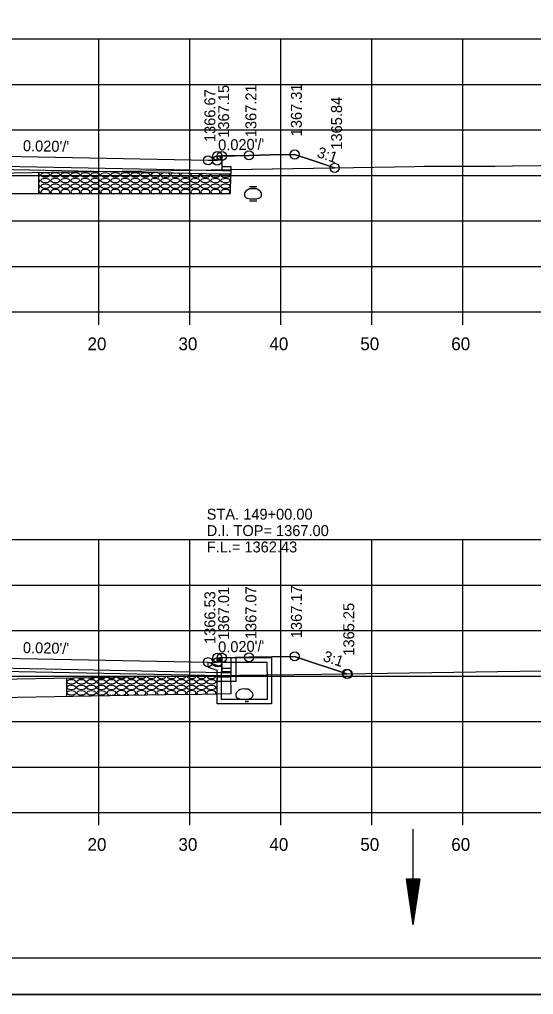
# Model space of a CAD drawing. Extents: x 1374311 to 1383814, y 384102 to 406278.
# Drawn here: x 1381639.9 to 1381696.4, y 391364.8 to 391471.9 of the extents above; entities that cross this region are included whole.
import ezdxf

# ---------------------------------------------------------------- set-up
doc = ezdxf.new("R2010")
doc.units = 0
for name, color, linetype in [('R_Axis', 7, 'Continuous'), ('R_Axis Annot', 7, 'Continuous'), ('R_Border', 7, 'Continuous'), ('R_Draft', 7, 'Continuous'), ('R_Exist Surface', 7, 'Continuous'), ('R_Fin Surface', 7, 'Continuous'), ('R_Grid', 7, 'Continuous'), ('R_No Plot', 7, 'Continuous'), ('R_Water', 7, 'Continuous'), ('R_Water Annot', 7, 'Continuous'), ('R_Xsect Elev', 7, 'Continuous'), ('R_Xsect Slope', 7, 'Continuous')]:
    doc.layers.add(name, color=color, linetype=linetype)

msp = doc.modelspace()

# ---------------------------------------------------------------- linework, layer by layer
at = {"layer": 'R_Axis'}
for p, q in [((1381488.66, 391439.74), (1381768.66, 391439.74)), ((1381648.66, 391438.34), (1381648.66, 391439.74)), ((1381658.66, 391438.34), (1381658.66, 391439.74)), ((1381668.66, 391438.34), (1381668.66, 391439.74)), ((1381678.66, 391438.34), (1381678.66, 391439.74)), ((1381688.66, 391438.34), (1381688.66, 391439.74)), ((1381488.66, 391384.74), (1381768.66, 391384.74)), ((1381648.66, 391383.34), (1381648.66, 391384.74)), ((1381658.66, 391383.34), (1381658.66, 391384.74)), ((1381668.66, 391383.34), (1381668.66, 391384.74)), ((1381678.66, 391383.34), (1381678.66, 391384.74)), ((1381688.66, 391383.34), (1381688.66, 391384.74))]:
    msp.add_line(p, q, dxfattribs=at)
at = {"layer": 'R_Border'}
msp.add_line((1381786.84, 391368.74), (1381470.66, 391368.74), dxfattribs=at)
at = {"layer": 'R_Draft'}
for p, q in [((1381682.43, 391377.42), (1381683.18, 391372.42)), ((1381683.93, 391377.42), (1381682.43, 391377.42)), ((1381682.56, 391377.42), (1381683.18, 391373.25)), ((1381682.68, 391377.42), (1381683.18, 391374.11)), ((1381682.81, 391377.42), (1381683.18, 391374.94)), ((1381682.94, 391377.42), (1381683.18, 391375.79)), ((1381683.06, 391377.42), (1381683.18, 391376.63)), ((1381683.93, 391377.42), (1381683.18, 391372.42)), ((1381683.42, 391377.42), (1381683.18, 391375.79)), ((1381683.68, 391377.42), (1381683.18, 391374.11)), ((1381683.81, 391377.42), (1381683.18, 391373.25)), ((1381683.55, 391377.42), (1381683.18, 391374.94)), ((1381683.3, 391377.42), (1381683.18, 391376.63))]:
    msp.add_line(p, q, dxfattribs=at)
for centre, radius, start, end in [((1381665.09, 391452.66), 0.438, 136.3515, 253.9529), ((1381665.6, 391452.17), 1.15, 43.6485, 136.3515), ((1381666.11, 391452.66), 0.438, 286.0471, 43.6485), ((1381665.6, 391454.44), 2.29, 253.9529, 286.0471), ((1381664.14, 391397.68), 0.438, 136.3515, 253.9529), ((1381664.65, 391397.19), 1.15, 43.6485, 136.3515), ((1381665.17, 391397.68), 0.438, 286.0471, 43.6485), ((1381664.65, 391399.46), 2.29, 253.9529, 286.0471)]:
    msp.add_arc(centre, radius, start, end, dxfattribs=at)
at = {"layer": 'R_Exist Surface'}
for p, q in [((1381665.23, 391453.53), (1381666.02, 391453.52)), ((1381665.23, 391451.95), (1381666.02, 391451.94)), ((1381664.73, 391396.96), (1381665.11, 391396.95))]:
    msp.add_line(p, q, dxfattribs=at)
for points in [[(1381559.74, 391452.62), (1381573.99, 391454.36), (1381575.4, 391454.36), (1381576.5, 391454.37), (1381590.51, 391454.48), (1381603.46, 391454.58), (1381605.2, 391454.59), (1381608.1, 391454.61), (1381615.77, 391454.74), (1381621.68, 391454.81), (1381630.21, 391454.93), (1381637.25, 391454.98), (1381643.34, 391455.11), (1381653.76, 391455.26), (1381656.57, 391455.29), (1381658.85, 391455.32), (1381683.36, 391455.73), (1381684.37, 391455.74), (1381692.19, 391455.77), (1381694.13, 391455.81), (1381706.41, 391455.95)], [(1381570.44, 391398.47), (1381574.42, 391398.46), (1381589.58, 391398.95), (1381591.76, 391398.74), (1381596.26, 391398.17), (1381598.15, 391398.32), (1381598.98, 391399.25), (1381613.79, 391399.74), (1381615.11, 391399.79), (1381620.09, 391399.77), (1381625.2, 391399.68), (1381632.44, 391399.29), (1381633.02, 391399.3), (1381633.51, 391399.32), (1381635.56, 391399.36), (1381655.94, 391399.73), (1381659.94, 391399.76), (1381664.06, 391399.82), (1381673.13, 391399.94), (1381694.93, 391400.26), (1381702.66, 391400.35)]]:
    msp.add_lwpolyline(points, dxfattribs=at)
at = {"layer": 'R_Fin Surface'}
for p, q in [((1381642.02, 391455.08), (1381642.02, 391452.74)), ((1381645.1, 391399.53), (1381645.1, 391397.53))]:
    msp.add_line(p, q, dxfattribs=at)
for points in [[(1381662.17, 391456.52), (1381662.18, 391455.37), (1381663.18, 391455.37), (1381663.17, 391454.87), (1381662.17, 391454.89), (1381628.66, 391455.56), (1381595.15, 391456.16), (1381594.15, 391456.18), (1381594.16, 391456.68), (1381595.16, 391456.65), (1381595.15, 391457.74)], [(1381628.66, 391457.04), (1381643.89, 391456.74), (1381660.66, 391456.4), (1381661.13, 391456.4), (1381661.66, 391456.38), (1381661.67, 391456.62), (1381661.67, 391456.88), (1381661.94, 391456.88), (1381662.17, 391456.88), (1381663.59, 391456.91), (1381665.17, 391456.94), (1381667.53, 391456.99), (1381670.17, 391457.04), (1381672.19, 391456.37), (1381674.59, 391455.57)], [(1381594.08, 391454.51), (1381594.08, 391452.74), (1381663.13, 391452.74), (1381663.17, 391454.87)], [(1381573.67, 391398.46), (1381587.15, 391402.95), (1381592.15, 391402.85), (1381595.15, 391402.79), (1381595.65, 391402.79), (1381595.66, 391402.29), (1381596.66, 391402.31), (1381628.66, 391401.9), (1381660.66, 391401.26), (1381661.66, 391401.24), (1381661.67, 391401.74), (1381662.17, 391401.74), (1381665.17, 391401.8), (1381670.17, 391401.9), (1381675.93, 391399.98)], [(1381662.17, 391401.38), (1381662.18, 391400.23), (1381663.18, 391400.23), (1381663.17, 391399.73), (1381662.17, 391399.75), (1381628.66, 391400.42), (1381595.15, 391400.89), (1381594.15, 391400.91), (1381594.16, 391401.41), (1381595.16, 391401.38), (1381595.15, 391402.48)], [(1381594.06, 391398.44), (1381594.07, 391397.09), (1381613.86, 391397.75), (1381615.14, 391397.79), (1381620.07, 391397.77), (1381625.13, 391397.68), (1381632.41, 391397.29), (1381633.09, 391397.3), (1381633.57, 391397.32), (1381635.6, 391397.36), (1381655.97, 391397.73), (1381659.96, 391397.76), (1381663.21, 391397.81), (1381663.17, 391399.73)]]:
    msp.add_lwpolyline(points, dxfattribs=at)
for centre, start_param, end_param in [((1381641.66, 391454.79), 5.506406, 7.059965), ((1381646.07, 391455.41), 4.548724, 4.931461), ((1381647.17, 391455.41), 4.339441, 5.140744), ((1381648.27, 391455.41), 4.267711, 5.079843), ((1381654.87, 391454.79), 1.829771, 7.517782), ((1381655.97, 391454.79), 2.045494, 7.302059), ((1381657.07, 391454.79), 2.198343, 7.14921), ((1381658.17, 391454.79), 2.325792, 7.021762), ((1381659.27, 391454.79), 2.438875, 6.908679), ((1381660.37, 391454.79), 2.54269, 6.804864), ((1381661.47, 391454.79), 2.64012, 6.707434), ((1381662.57, 391454.79), 2.733011, 6.614542), ((1381641.66, 391454.17), 5.506406, 7.059965), ((1381641.66, 391453.55), 5.506406, 7.059965), ((1381641.66, 391452.93), 5.506406, 7.059965), ((1381642.76, 391452.93), 5.41975, 10.288213), ((1381643.87, 391452.93), 5.41975, 10.288213), ((1381644.97, 391452.93), 5.41975, 10.288213), ((1381646.07, 391452.93), 5.41975, 10.288213), ((1381647.17, 391452.93), 5.41975, 10.288213), ((1381648.27, 391452.93), 5.41975, 10.288213), ((1381649.37, 391452.93), 5.41975, 10.288213), ((1381650.47, 391452.93), 5.41975, 10.288213), ((1381651.57, 391452.93), 5.41975, 10.288213), ((1381652.67, 391452.93), 5.41975, 10.288213), ((1381653.77, 391452.93), 5.41975, 10.288213), ((1381654.87, 391452.93), 5.41975, 10.288213), ((1381655.97, 391452.93), 5.41975, 10.288213), ((1381657.07, 391452.93), 5.41975, 10.288213), ((1381658.17, 391452.93), 5.41975, 10.288213), ((1381659.27, 391452.93), 5.41975, 10.288213), ((1381660.37, 391452.93), 5.41975, 10.288213), ((1381661.47, 391452.93), 5.41975, 10.288213), ((1381662.57, 391452.93), 5.41975, 10.288213), ((1381645.63, 391399.73), 4.001346, 5.493252), ((1381646.73, 391399.73), 3.894207, 5.600391), ((1381647.83, 391399.73), 3.796303, 5.698295), ((1381648.93, 391399.73), 3.704829, 5.78977), ((1381650.03, 391399.73), 3.618011, 5.876587), ((1381651.13, 391399.73), 3.534628, 5.95997), ((1381652.23, 391399.73), 3.453777, 6.040822), ((1381653.33, 391399.73), 3.374749, 6.119849), ((1381654.43, 391399.73), 3.29696, 6.197639), ((1381655.53, 391399.73), 3.219898, 6.271446), ((1381656.63, 391399.73), 3.150088, 6.307116), ((1381657.73, 391399.73), 3.114409, 6.300849), ((1381657.73, 391399.73), 0.017664, 0.059611), ((1381658.83, 391399.73), 3.078673, 6.363554), ((1381658.83, 391399.73), 0.080369, 0.095346), ((1381659.93, 391399.73), 3.042836, 6.414368), ((1381659.93, 391399.73), 0.131183, 0.143279), ((1381661.03, 391399.73), 2.991936, 6.398491), ((1381662.13, 391399.11), 2.832405, 3.45078), ((1381662.13, 391399.73), 3.034539, 3.45078), ((1381650.03, 391397.88), 4.881698, 10.318639), ((1381650.03, 391397.88), 4.035454, 4.6129), ((1381651.13, 391397.88), 5.164572, 10.264554), ((1381651.13, 391397.88), 3.981369, 4.330026), ((1381652.23, 391397.88), 5.325563, 10.21346), ((1381652.23, 391397.88), 3.930275, 4.169036), ((1381653.33, 391397.88), 5.453815, 10.164794), ((1381653.33, 391397.88), 3.881609, 4.040784), ((1381654.43, 391397.88), 5.565077, 10.118139), ((1381654.43, 391397.88), 3.834954, 3.929521), ((1381655.53, 391397.88), 5.66574, 10.073173), ((1381655.53, 391397.88), 3.789988, 3.828858), ((1381656.63, 391397.88), 1.325946, 3.746458), ((1381656.63, 391397.88), 5.710747, 7.609131), ((1381657.73, 391397.88), 5.753046, 9.930366), ((1381657.73, 391397.88), 3.647181, 3.704158), ((1381658.83, 391397.88), 5.794284, 9.845926), ((1381658.83, 391397.88), 3.562741, 3.66292), ((1381659.93, 391397.88), 5.846214, 9.764299), ((1381659.93, 391397.88), 3.481114, 3.622603), ((1381661.03, 391397.88), 5.915217, 9.68472), ((1381661.03, 391397.88), 3.401535, 3.566553), ((1381662.13, 391398.49), 2.832405, 3.45078), ((1381662.13, 391397.88), 2.832405, 3.45078)]:
    msp.add_ellipse(centre, major_axis=(0.5, 0), ratio=0.517889, start_param=start_param, end_param=end_param, dxfattribs=at)
for centre in [(1381642.76, 391454.79), (1381643.87, 391454.79), (1381644.97, 391454.79), (1381646.07, 391454.79), (1381647.17, 391454.79), (1381648.27, 391454.79), (1381649.37, 391454.79), (1381650.47, 391454.79), (1381651.57, 391454.79), (1381652.67, 391454.79), (1381653.77, 391454.79), (1381642.76, 391454.17), (1381642.76, 391453.55), (1381643.87, 391454.17), (1381643.87, 391453.55), (1381644.97, 391454.17), (1381644.97, 391453.55), (1381646.07, 391454.17), (1381646.07, 391453.55), (1381647.17, 391454.17), (1381647.17, 391453.55), (1381648.27, 391454.17), (1381648.27, 391453.55), (1381649.37, 391454.17), (1381649.37, 391453.55), (1381650.47, 391454.17), (1381650.47, 391453.55), (1381651.57, 391454.17), (1381651.57, 391453.55), (1381652.67, 391454.17), (1381652.67, 391453.55), (1381653.77, 391454.17), (1381653.77, 391453.55), (1381654.87, 391454.17), (1381654.87, 391453.55), (1381655.97, 391454.17), (1381655.97, 391453.55), (1381657.07, 391454.17), (1381657.07, 391453.55), (1381658.17, 391454.17), (1381658.17, 391453.55), (1381659.27, 391454.17), (1381659.27, 391453.55), (1381660.37, 391454.17), (1381660.37, 391453.55), (1381661.47, 391454.17), (1381661.47, 391453.55), (1381662.57, 391454.17), (1381662.57, 391453.55), (1381645.63, 391399.11), (1381645.63, 391398.49), (1381646.73, 391399.11), (1381646.73, 391398.49), (1381647.83, 391399.11), (1381647.83, 391398.49), (1381648.93, 391399.11), (1381648.93, 391398.49), (1381650.03, 391399.11), (1381650.03, 391398.49), (1381651.13, 391399.11), (1381651.13, 391398.49), (1381652.23, 391399.11), (1381652.23, 391398.49), (1381653.33, 391399.11), (1381653.33, 391398.49), (1381654.43, 391399.11), (1381654.43, 391398.49), (1381655.53, 391399.11), (1381655.53, 391398.49), (1381656.63, 391399.11), (1381656.63, 391398.49), (1381657.73, 391399.11), (1381657.73, 391398.49), (1381658.83, 391399.11), (1381658.83, 391398.49), (1381659.93, 391399.11), (1381659.93, 391398.49), (1381661.03, 391399.11), (1381661.03, 391398.49), (1381645.63, 391397.88), (1381646.73, 391397.88), (1381647.83, 391397.88), (1381648.93, 391397.88)]:
    msp.add_ellipse(centre, major_axis=(0.5, 0), ratio=0.517889, dxfattribs=at)
at = {"layer": 'R_Grid'}
for p, q in [((1381488.66, 391469.74), (1381768.66, 391469.74)), ((1381648.66, 391439.74), (1381648.66, 391469.74)), ((1381658.66, 391439.74), (1381658.66, 391469.74)), ((1381668.66, 391439.74), (1381668.66, 391469.74)), ((1381678.66, 391439.74), (1381678.66, 391469.74)), ((1381688.66, 391439.74), (1381688.66, 391469.74)), ((1381488.66, 391464.74), (1381768.66, 391464.74)), ((1381488.66, 391459.74), (1381768.66, 391459.74)), ((1381488.66, 391454.74), (1381768.66, 391454.74)), ((1381488.66, 391449.74), (1381768.66, 391449.74)), ((1381488.66, 391444.74), (1381768.66, 391444.74)), ((1381488.66, 391439.74), (1381768.66, 391439.74)), ((1381488.66, 391414.74), (1381768.66, 391414.74)), ((1381648.66, 391384.74), (1381648.66, 391414.74)), ((1381658.66, 391384.74), (1381658.66, 391414.74)), ((1381668.66, 391384.74), (1381668.66, 391414.74)), ((1381678.66, 391384.74), (1381678.66, 391414.74)), ((1381688.66, 391384.74), (1381688.66, 391414.74)), ((1381488.66, 391409.74), (1381768.66, 391409.74)), ((1381488.66, 391404.74), (1381768.66, 391404.74)), ((1381488.66, 391399.74), (1381768.66, 391399.74)), ((1381488.66, 391394.74), (1381768.66, 391394.74)), ((1381488.66, 391389.74), (1381768.66, 391389.74)), ((1381488.66, 391384.74), (1381768.66, 391384.74))]:
    msp.add_line(p, q, dxfattribs=at)
at = {"layer": 'R_No Plot'}
msp.add_line((1381458.26, 391364.76), (1381791.59, 391364.76), dxfattribs=at)
for points in [[(1381458.25, 391578.09), (1381791.59, 391578.09), (1381791.59, 391364.75), (1381458.25, 391364.75)], [(1381704.58, 391574.2), (1381704.58, 391564.32), (1381740.31, 391564.32), (1381740.31, 391561.4), (1381763.51, 391561.4), (1381763.51, 391538.18), (1381786.84, 391538.18), (1381786.84, 391368.74), (1381470.66, 391368.74), (1381470.66, 391574.2)], [(1381663.18, 391455.39), (1381674.57, 391455.58), (1381672.19, 391456.37), (1381670.17, 391457.04), (1381667.53, 391456.99), (1381665.17, 391456.94), (1381663.59, 391456.91), (1381662.17, 391456.88), (1381662.18, 391455.73), (1381663.18, 391455.73)], [(1381658.72, 391455.32), (1381658.85, 391455.32), (1381663.18, 391455.39), (1381663.17, 391455.23), (1381662.17, 391455.25)]]:
    msp.add_lwpolyline(points, close=True, dxfattribs=at)
for points in [[(1381637.25, 391454.98), (1381643.34, 391455.11), (1381653.76, 391455.26), (1381656.57, 391455.29), (1381658.72, 391455.32), (1381628.66, 391455.92)], [(1381635.56, 391399.36), (1381655.94, 391399.73), (1381659.94, 391399.76), (1381664.06, 391399.82), (1381673.13, 391399.94), (1381675.93, 391399.98), (1381670.17, 391401.9), (1381665.17, 391401.8), (1381662.17, 391401.74), (1381662.18, 391400.59), (1381663.18, 391400.59), (1381663.17, 391400.09), (1381662.17, 391400.11), (1381628.66, 391400.78)]]:
    msp.add_lwpolyline(points, dxfattribs=at)
for centre in [(1381660.66, 391456.4), (1381660.66, 391456.4), (1381660.66, 391456.4), (1381661.66, 391456.38), (1381661.67, 391456.88), (1381661.67, 391456.88), (1381661.67, 391456.88), (1381662.17, 391456.88), (1381662.17, 391456.88), (1381662.17, 391456.88), (1381665.17, 391456.94), (1381665.17, 391456.94), (1381665.17, 391456.94), (1381670.17, 391457.04), (1381670.17, 391457.04), (1381670.17, 391457.04), (1381674.58, 391455.57), (1381674.59, 391455.57), (1381674.59, 391455.57), (1381661.67, 391401.74), (1381661.67, 391401.74), (1381661.67, 391401.74), (1381662.17, 391401.74), (1381662.17, 391401.74), (1381662.17, 391401.74), (1381665.17, 391401.8), (1381665.17, 391401.8), (1381665.17, 391401.8), (1381670.17, 391401.9), (1381670.17, 391401.9), (1381670.17, 391401.9), (1381660.66, 391401.26), (1381660.66, 391401.26), (1381660.66, 391401.26), (1381661.66, 391401.24), (1381675.93, 391399.98), (1381675.93, 391399.98), (1381676, 391399.96)]:
    msp.add_circle(centre, 0.5, dxfattribs=at)
at = {"layer": 'R_Water'}
for p, q in [((1381665.23, 391453.32), (1381666.02, 391453.31)), ((1381665.23, 391452.16), (1381666.02, 391452.14)), ((1381660.66, 391401.26), (1381662.16, 391400.74)), ((1381661.82, 391401.58), (1381661.91, 391401.74)), ((1381661.82, 391401.58), (1381662.16, 391401.24)), ((1381667.66, 391401.74), (1381661.91, 391401.74)), ((1381667.16, 391401.24), (1381662.16, 391401.24)), ((1381667.16, 391400.24), (1381667.16, 391401.24)), ((1381667.66, 391400.24), (1381667.66, 391401.74)), ((1381660.66, 391400.73), (1381661.66, 391400.38)), ((1381661.66, 391400.24), (1381661.66, 391400.38)), ((1381662.16, 391400.24), (1381662.16, 391400.74)), ((1381664.73, 391398.33), (1381665.11, 391398.33)), ((1381664.73, 391397.17), (1381665.11, 391397.16)), ((1381683.18, 391382.92), (1381683.18, 391372.42))]:
    msp.add_line(p, q, dxfattribs=at)
for points in [[(1381660.66, 391400.73), (1381660.66, 391401.26)], [(1381663.71, 391401.68), (1381663.71, 391399.15), (1381661.71, 391399.15), (1381661.71, 391399.65), (1381663.21, 391399.65), (1381663.21, 391401.67)], [(1381667.65, 391400.24), (1381667.65, 391396.67), (1381664.65, 391396.67), (1381661.65, 391396.67), (1381661.65, 391400.24)], [(1381667.15, 391400.24), (1381667.15, 391397.17), (1381664.65, 391397.17), (1381662.15, 391397.17), (1381662.15, 391400.24)]]:
    msp.add_lwpolyline(points, dxfattribs=at)

# ---------------------------------------------------------------- texts
at = {"layer": 'R_Axis Annot'}
for s, p in [('20', (1381647.4, 391435.54)), ('30', (1381657.4, 391435.54)), ('40', (1381667.4, 391435.54)), ('50', (1381677.4, 391435.54)), ('60', (1381687.4, 391435.54)), ('20', (1381647.4, 391380.54)), ('30', (1381657.4, 391380.54)), ('40', (1381667.4, 391380.54)), ('50', (1381677.4, 391380.54)), ('60', (1381687.4, 391380.54))]:
    msp.add_text(s, height=1.4, dxfattribs=at).set_placement(p)
at = {"layer": 'R_Water Annot'}
for s, p in [('STA. 149+00.00', (1381660.51, 391416.92)), ('D.I. TOP= 1367.00', (1381660.51, 391415.12)), ('F.L.= 1362.43', (1381660.51, 391413.32))]:
    msp.add_text(s, height=1.2, dxfattribs=at).set_placement(p)
at = {"layer": 'R_Xsect Elev'}
for s, p in [('1366.67', (1381661.46, 391458.4)), ('1367.15', (1381662.97, 391458.88)), ('1367.21', (1381665.97, 391458.94)), ('1367.31', (1381670.97, 391459.04)), ('1365.84', (1381675.39, 391457.57)), ('1367.01', (1381662.97, 391403.74)), ('1367.07', (1381665.97, 391403.8)), ('1367.17', (1381670.97, 391403.9)), ('1366.53', (1381661.46, 391403.26)), ('1365.25', (1381676.73, 391401.98))]:
    msp.add_text(s, height=1.2, rotation=90, dxfattribs=at).set_placement(p)
at = {"layer": 'R_Xsect Slope'}
for s, rotation, p in [("0.020'/'", 1.1458, (1381661.78, 391457.48)), ("0.020'/'", 358.8542, (1381640.29, 391457.41)), ('3:1', 341.565, (1381672.54, 391456.78)), ("0.020'/'", 358.8542, (1381640.29, 391402.27)), ("0.020'/'", 1.1458, (1381661.78, 391402.33)), ('3:1', 341.5651, (1381673.21, 391401.42))]:
    msp.add_text(s, height=1.2, rotation=rotation, dxfattribs=at).set_placement(p)

doc.saveas('drawing.dxf')
